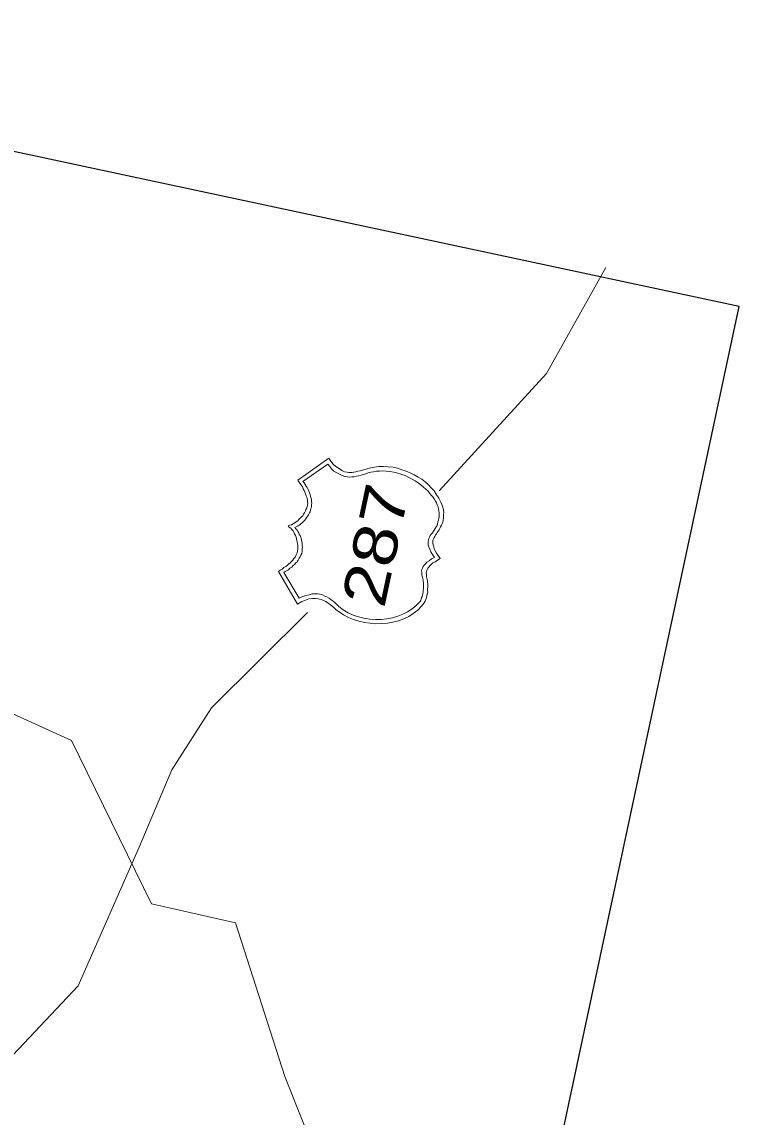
# Model space of a CAD drawing. Extents: x 2363411 to 2369126, y 6976878 to 6988319.
# Drawn here: x 2368470 to 2368553.7, y 6988102.7 to 6988230.5 of the extents above; entities that cross this region are included whole.
import ezdxf

# ---------------------------------------------------------------- set-up
doc = ezdxf.new("R2010")
doc.units = 0
doc.header["$LTSCALE"] = 2
doc.layers.add('62', color=7, linetype='Continuous', lineweight=13)
doc.layers.add('63', color=7, linetype='Continuous', lineweight=13)

msp = doc.modelspace()

# ---------------------------------------------------------------- linework, layer by layer
at = {"layer": '62'}
for p, q in [((2368538.15, 6988201.858), (2368531.227, 6988189.506)), ((2368531.227, 6988189.506), (2368518.7, 6988175.776)), ((2368492.126, 6988150.482), (2368503.332, 6988161.574))]:
    msp.add_line(p, q, dxfattribs=at)
at = {"layer": '62', "lineweight": 25}
msp.add_lwpolyline([(2368004.774, 6987854.862), (2368459.776, 6987757.642), (2368553.719, 6988197.31), (2368098.715, 6988294.53)], dxfattribs=at)
at = {"layer": '62'}
for points in [[(2368423.495, 6988182.612), (2368431.049, 6988175.317), (2368445.358, 6988162.592), (2368462.419, 6988152.736), (2368475.776, 6988146.66), (2368485.116, 6988127.592), (2368494.927, 6988125.354), (2368500.711, 6988107.416), (2368506.585, 6988092.7), (2368510.293, 6988075.479), (2368509.748, 6988052.675), (2368510.031, 6988033.104), (2368510.965, 6988011.643), (2368511.296, 6987998.756)], [(2368502.19, 6988162.579), (2368499.944, 6988166.392), (2368500.158, 6988166.532), (2368500.394, 6988166.664), (2368500.589, 6988166.829), (2368500.799, 6988166.946), (2368500.995, 6988167.114), (2368501.166, 6988167.26), (2368501.334, 6988167.408), (2368501.509, 6988167.577), (2368501.631, 6988167.713), (2368501.76, 6988167.892), (2368501.887, 6988168.049), (2368501.974, 6988168.239), (2368502.055, 6988168.405), (2368502.129, 6988168.549), (2368502.179, 6988168.77), (2368502.221, 6988168.967), (2368502.205, 6988169.11), (2368502.192, 6988169.272), (2368502.208, 6988169.452), (2368502.18, 6988169.643), (2368502.152, 6988169.835), (2368502.097, 6988170.006), (2368502.069, 6988170.198), (2368502.019, 6988170.391), (2368501.92, 6988170.573), (2368501.826, 6988170.778), (2368501.727, 6988170.96), (2368501.65, 6988171.136), (2368501.517, 6988171.281), (2368501.393, 6988171.445), (2368501.209, 6988171.554), (2368501.078, 6988171.696), (2368501.254, 6988171.773), (2368501.477, 6988171.842), (2368501.681, 6988171.936), (2368501.843, 6988172.04), (2368502.03, 6988172.162), (2368502.199, 6988172.307), (2368502.34, 6988172.439), (2368502.489, 6988172.591), (2368502.635, 6988172.742), (2368502.778, 6988172.875), (2368502.871, 6988173.084), (2368502.991, 6988173.222), (2368503.088, 6988173.453), (2368503.164, 6988173.598), (2368503.256, 6988173.808), (2368503.315, 6988173.981), (2368503.347, 6988174.134), (2368503.366, 6988174.336), (2368503.33, 6988174.483), (2368503.329, 6988174.688), (2368503.299, 6988174.88), (2368503.244, 6988175.054), (2368503.191, 6988175.227), (2368503.121, 6988175.448), (2368503.022, 6988175.631), (2368502.951, 6988175.828), (2368502.828, 6988176.016), (2368502.739, 6988176.242), (2368502.62, 6988176.431), (2368502.479, 6988176.643), (2368502.336, 6988176.835), (2368502.22, 6988177.044), (2368505.829, 6988179.61), (2368506.076, 6988179.257), (2368506.322, 6988178.905), (2368506.653, 6988178.626), (2368507.017, 6988178.389), (2368507.359, 6988178.154), (2368507.674, 6988178.015), (2368507.96, 6988177.956), (2368508.158, 6988177.914), (2368508.345, 6988177.921), (2368508.555, 6988177.946), (2368508.747, 6988177.972), (2368508.985, 6988178.013), (2368509.227, 6988178.076), (2368509.472, 6988178.14), (2368509.742, 6988178.222), (2368510.012, 6988178.301), (2368510.306, 6988178.375), (2368510.575, 6988178.457), (2368510.886, 6988178.505), (2368511.151, 6988178.563), (2368511.412, 6988178.599), (2368511.671, 6988178.636), (2368511.95, 6988178.646), (2368512.2, 6988178.637), (2368512.766, 6988178.586), (2368513.331, 6988178.537), (2368513.836, 6988178.427), (2368514.349, 6988178.248), (2368514.868, 6988178.092), (2368515.335, 6988177.9), (2368515.79, 6988177.664), (2368516.24, 6988177.406), (2368516.669, 6988177.155), (2368517.085, 6988176.835)], [(2368517.583, 6988175.51), (2368517.407, 6988175.754), (2368517.136, 6988175.998), (2368516.866, 6988176.238), (2368516.573, 6988176.484), (2368516.255, 6988176.714), (2368515.913, 6988176.948), (2368515.568, 6988177.161), (2368515.171, 6988177.358), (2368514.756, 6988177.564), (2368514.347, 6988177.696), (2368513.899, 6988177.859), (2368513.436, 6988177.962), (2368512.949, 6988178.042), (2368512.52, 6988178.086), (2368512.116, 6988178.128), (2368511.763, 6988178.089), (2368511.392, 6988178.074), (2368511.054, 6988178.009), (2368510.745, 6988177.961), (2368510.431, 6988177.889), (2368510.135, 6988177.79), (2368509.837, 6988177.694), (2368509.588, 6988177.609), (2368509.323, 6988177.551), (2368509.058, 6988177.493), (2368508.771, 6988177.438), (2368508.537, 6988177.42), (2368508.279, 6988177.406), (2368508.006, 6988177.417), (2368507.693, 6988177.461), (2368507.377, 6988177.598), (2368507.061, 6988177.735), (2368506.75, 6988177.894), (2368506.427, 6988178.1), (2368506.177, 6988178.337), (2368505.938, 6988178.619), (2368505.699, 6988178.9), (2368502.809, 6988176.895), (2368502.931, 6988176.71), (2368503.057, 6988176.542), (2368503.2, 6988176.352), (2368503.3, 6988176.169), (2368503.415, 6988175.962), (2368503.487, 6988175.761), (2368503.56, 6988175.563), (2368503.632, 6988175.361), (2368503.7, 6988175.14), (2368503.772, 6988174.941), (2368503.796, 6988174.727), (2368503.802, 6988174.544), (2368503.832, 6988174.351), (2368503.82, 6988174.194), (2368503.81, 6988174.037), (2368503.8, 6988173.876), (2368503.744, 6988173.728), (2368503.683, 6988173.555), (2368503.642, 6988173.359), (2368503.564, 6988173.212), (2368503.451, 6988173.007), (2368503.375, 6988172.862), (2368503.27, 6988172.7), (2368503.142, 6988172.521), (2368503.019, 6988172.386), (2368502.889, 6988172.207), (2368502.752, 6988172.099), (2368502.585, 6988171.973), (2368502.438, 6988171.821), (2368502.256, 6988171.723), (2368502.075, 6988171.622), (2368501.87, 6988171.529), (2368501.995, 6988171.363), (2368502.143, 6988171.195), (2368502.225, 6988171.038), (2368502.329, 6988170.877), (2368502.384, 6988170.705), (2368502.47, 6988170.571), (2368502.544, 6988170.371), (2368502.603, 6988170.221), (2368502.637, 6988170.052), (2368502.688, 6988169.857), (2368502.703, 6988169.715), (2368502.708, 6988169.532), (2368502.72, 6988169.368), (2368502.753, 6988169.199), (2368502.715, 6988169.023), (2368502.726, 6988168.861), (2368502.716, 6988168.7), (2368502.668, 6988168.481), (2368502.56, 6988168.298), (2368502.49, 6988168.081), (2368502.364, 6988167.924), (2368502.253, 6988167.717), (2368502.117, 6988167.519), (2368501.973, 6988167.386), (2368501.817, 6988167.19), (2368501.643, 6988167.021), (2368501.495, 6988166.869), (2368501.284, 6988166.75), (2368501.112, 6988166.582), (2368500.903, 6988166.463)], [(2368517.085, 6988176.835), (2368517.45, 6988176.503), (2368517.764, 6988176.138), (2368518.127, 6988175.784), (2368518.397, 6988175.334), (2368518.68, 6988174.929), (2368518.904, 6988174.469), (2368519.01, 6988174.215), (2368519.1, 6988173.991), (2368519.162, 6988173.745), (2368519.203, 6988173.507), (2368519.25, 6988173.29), (2368519.224, 6988173.065), (2368519.218, 6988172.812), (2368519.218, 6988172.608), (2368519.166, 6988172.363), (2368519.119, 6988172.142), (2368519.054, 6988171.952), (2368518.995, 6988171.78), (2368518.882, 6988171.575), (2368518.801, 6988171.407), (2368518.72, 6988171.24), (2368518.593, 6988171.083), (2368518.49, 6988170.923), (2368518.387, 6988170.759), (2368518.292, 6988170.642), (2368518.19, 6988170.48), (2368518.138, 6988170.352), (2368518.056, 6988170.185), (2368517.975, 6988170.021), (2368517.965, 6988169.859), (2368517.972, 6988169.674), (2368517.994, 6988169.462), (2368518.067, 6988169.263), (2368518.134, 6988169.042), (2368518.241, 6988168.788), (2368518.392, 6988168.526), (2368518.604, 6988168.227), (2368518.833, 6988167.902), (2368518.513, 6988167.693), (2368518.247, 6988167.523), (2368517.984, 6988167.37), (2368517.783, 6988167.184), (2368517.62, 6988167.057), (2368517.494, 6988166.9), (2368517.393, 6988166.76), (2368517.318, 6988166.617), (2368517.266, 6988166.489), (2368517.234, 6988166.334), (2368517.206, 6988166.203), (2368517.217, 6988166.041), (2368517.237, 6988165.922), (2368517.227, 6988165.761), (2368517.282, 6988165.59), (2368517.297, 6988165.447), (2368517.335, 6988165.302), (2368517.347, 6988165.138), (2368517.374, 6988164.948), (2368517.376, 6988164.739), (2368517.382, 6988164.554), (2368517.362, 6988164.351), (2368517.366, 6988164.144), (2368517.372, 6988163.961), (2368517.323, 6988163.74), (2368517.281, 6988163.541), (2368517.239, 6988163.341), (2368517.145, 6988163.109), (2368517.057, 6988162.92), (2368516.944, 6988162.715), (2368516.809, 6988162.514), (2368516.651, 6988162.317), (2368516.213, 6988161.881), (2368515.691, 6988161.485), (2368515.153, 6988161.118), (2368514.566, 6988160.852), (2368513.943, 6988160.617), (2368513.308, 6988160.454), (2368512.668, 6988160.362), (2368511.987, 6988160.299), (2368511.317, 6988160.281), (2368510.659, 6988160.329), (2368509.989, 6988160.427), (2368509.35, 6988160.562), (2368508.725, 6988160.765), (2368508.137, 6988161.007), (2368507.556, 6988161.315), (2368507.053, 6988161.652), (2368506.851, 6988161.787), (2368506.633, 6988161.948), (2368506.441, 6988162.128), (2368506.207, 6988162.315), (2368505.972, 6988162.507), (2368505.736, 6988162.692), (2368505.494, 6988162.861), (2368505.223, 6988162.986), (2368504.929, 6988163.118), (2368504.598, 6988163.191), (2368504.264, 6988163.238), (2368503.914, 6988163.221), (2368503.512, 6988163.169), (2368503.096, 6988163.05)], [(2368500.583, 6988166.258), (2368502.357, 6988163.255), (2368502.767, 6988163.443), (2368503.166, 6988163.587), (2368503.528, 6988163.671), (2368503.868, 6988163.76), (2368504.212, 6988163.754), (2368504.512, 6988163.76), (2368504.78, 6988163.725), (2368505.085, 6988163.639), (2368505.358, 6988163.511), (2368505.611, 6988163.41), (2368505.858, 6988163.265), (2368506.094, 6988163.076), (2368506.333, 6988162.912), (2368506.568, 6988162.723), (2368506.779, 6988162.518), (2368507.009, 6988162.306), (2368507.519, 6988161.898), (2368508.095, 6988161.568), (2368508.655, 6988161.287), (2368509.3, 6988161.08), (2368509.934, 6988160.922), (2368510.598, 6988160.802), (2368511.283, 6988160.771), (2368511.927, 6988160.772), (2368512.585, 6988160.838), (2368513.258, 6988160.97), (2368513.876, 6988161.162), (2368514.474, 6988161.379), (2368515.018, 6988161.676), (2368515.548, 6988162.001), (2368516, 6988162.387), (2368516.406, 6988162.783), (2368516.473, 6988162.883), (2368516.569, 6988163.001), (2368516.622, 6988163.152), (2368516.66, 6988163.328), (2368516.71, 6988163.454), (2368516.749, 6988163.632), (2368516.787, 6988163.808), (2368516.824, 6988163.984), (2368516.845, 6988164.186), (2368516.876, 6988164.341), (2368516.876, 6988164.545), (2368516.89, 6988164.728), (2368516.881, 6988164.892), (2368516.874, 6988165.077), (2368516.84, 6988165.246), (2368516.846, 6988165.382), (2368516.787, 6988165.534), (2368516.752, 6988165.701), (2368516.713, 6988165.826), (2368516.677, 6988165.993), (2368516.667, 6988166.157), (2368516.674, 6988166.294), (2368516.663, 6988166.456), (2368516.694, 6988166.611), (2368516.771, 6988166.756), (2368516.858, 6988166.946), (2368516.939, 6988167.111), (2368517.108, 6988167.257), (2368517.288, 6988167.451), (2368517.555, 6988167.623), (2368517.831, 6988167.84), (2368518.148, 6988168.026), (2368517.922, 6988168.373), (2368517.737, 6988168.689), (2368517.613, 6988168.967), (2368517.511, 6988169.244), (2368517.442, 6988169.466), (2368517.441, 6988169.673), (2368517.434, 6988169.858), (2368517.481, 6988170.079), (2368517.514, 6988170.233), (2368517.591, 6988170.377), (2368517.677, 6988170.565), (2368517.78, 6988170.727), (2368517.902, 6988170.864), (2368518.004, 6988171.025), (2368518.115, 6988171.207), (2368518.246, 6988171.388), (2368518.354, 6988171.572), (2368518.46, 6988171.753), (2368518.526, 6988171.948), (2368518.572, 6988172.169), (2368518.637, 6988172.364), (2368518.663, 6988172.588), (2368518.704, 6988172.785), (2368518.707, 6988173.014), (2368518.711, 6988173.244), (2368518.687, 6988173.456), (2368518.624, 6988173.7), (2368518.578, 6988173.917), (2368518.488, 6988174.142), (2368518.404, 6988174.391), (2368518.265, 6988174.605), (2368518.108, 6988174.845), (2368517.993, 6988175.054), (2368517.788, 6988175.282), (2368517.583, 6988175.51)], [(2368500.903, 6988166.463), (2368500.744, 6988166.36), (2368500.583, 6988166.258)], [(2368503.096, 6988163.05), (2368502.666, 6988162.865), (2368502.19, 6988162.579)], [(2368492.126, 6988150.482), (2368487.488, 6988143.215), (2368483.673, 6988134.181), (2368476.579, 6988118.002), (2368468.319, 6988109.277), (2368462.564, 6988103.439), (2368454.914, 6988095.96), (2368443.897, 6988089.32), (2368432.645, 6988085.443), (2368420.226, 6988082.021), (2368405.209, 6988076.579), (2368395.275, 6988071.108), (2368385.769, 6988067.316), (2368374.006, 6988063.41), (2368368.396, 6988060.537), (2368354.465, 6988056.288)]]:
    msp.add_lwpolyline(points, dxfattribs=at)
at = {"layer": '63'}
for p, q in [((2368538.15, 6988201.858), (2368531.227, 6988189.506)), ((2368531.227, 6988189.506), (2368518.7, 6988175.776)), ((2368492.126, 6988150.482), (2368503.332, 6988161.574))]:
    msp.add_line(p, q, dxfattribs=at)
at = {"layer": '63', "lineweight": 25}
msp.add_lwpolyline([(2368004.774, 6987854.862), (2368459.776, 6987757.642), (2368553.719, 6988197.31), (2368098.715, 6988294.53)], dxfattribs=at)
at = {"layer": '63'}
for points in [[(2368423.495, 6988182.612), (2368431.049, 6988175.317), (2368445.358, 6988162.592), (2368462.419, 6988152.736), (2368475.776, 6988146.66), (2368485.116, 6988127.592), (2368494.927, 6988125.354), (2368500.711, 6988107.416), (2368506.585, 6988092.7), (2368510.293, 6988075.479), (2368509.748, 6988052.675), (2368510.031, 6988033.104), (2368510.965, 6988011.643), (2368511.296, 6987998.756)], [(2368502.19, 6988162.579), (2368499.944, 6988166.392), (2368500.158, 6988166.532), (2368500.394, 6988166.664), (2368500.589, 6988166.829), (2368500.799, 6988166.946), (2368500.995, 6988167.114), (2368501.166, 6988167.26), (2368501.334, 6988167.408), (2368501.509, 6988167.577), (2368501.631, 6988167.713), (2368501.76, 6988167.892), (2368501.887, 6988168.049), (2368501.974, 6988168.239), (2368502.055, 6988168.405), (2368502.129, 6988168.549), (2368502.179, 6988168.77), (2368502.221, 6988168.967), (2368502.205, 6988169.11), (2368502.192, 6988169.272), (2368502.208, 6988169.452), (2368502.18, 6988169.643), (2368502.152, 6988169.835), (2368502.097, 6988170.006), (2368502.069, 6988170.198), (2368502.019, 6988170.391), (2368501.92, 6988170.573), (2368501.826, 6988170.778), (2368501.727, 6988170.96), (2368501.65, 6988171.136), (2368501.517, 6988171.281), (2368501.393, 6988171.445), (2368501.209, 6988171.554), (2368501.078, 6988171.696), (2368501.254, 6988171.773), (2368501.477, 6988171.842), (2368501.681, 6988171.936), (2368501.843, 6988172.04), (2368502.03, 6988172.162), (2368502.199, 6988172.307), (2368502.34, 6988172.439), (2368502.489, 6988172.591), (2368502.635, 6988172.742), (2368502.778, 6988172.875), (2368502.871, 6988173.084), (2368502.991, 6988173.222), (2368503.088, 6988173.453), (2368503.164, 6988173.598), (2368503.256, 6988173.808), (2368503.315, 6988173.981), (2368503.347, 6988174.134), (2368503.366, 6988174.336), (2368503.33, 6988174.483), (2368503.329, 6988174.688), (2368503.299, 6988174.88), (2368503.244, 6988175.054), (2368503.191, 6988175.227), (2368503.121, 6988175.448), (2368503.022, 6988175.631), (2368502.951, 6988175.828), (2368502.828, 6988176.016), (2368502.739, 6988176.242), (2368502.62, 6988176.431), (2368502.479, 6988176.643), (2368502.336, 6988176.835), (2368502.22, 6988177.044), (2368505.829, 6988179.61), (2368506.076, 6988179.257), (2368506.322, 6988178.905), (2368506.653, 6988178.626), (2368507.017, 6988178.389), (2368507.359, 6988178.154), (2368507.674, 6988178.015), (2368507.96, 6988177.956), (2368508.158, 6988177.914), (2368508.345, 6988177.921), (2368508.555, 6988177.946), (2368508.747, 6988177.972), (2368508.985, 6988178.013), (2368509.227, 6988178.076), (2368509.472, 6988178.14), (2368509.742, 6988178.222), (2368510.012, 6988178.301), (2368510.306, 6988178.375), (2368510.575, 6988178.457), (2368510.886, 6988178.505), (2368511.151, 6988178.563), (2368511.412, 6988178.599), (2368511.671, 6988178.636), (2368511.95, 6988178.646), (2368512.2, 6988178.637), (2368512.766, 6988178.586), (2368513.331, 6988178.537), (2368513.836, 6988178.427), (2368514.349, 6988178.248), (2368514.868, 6988178.092), (2368515.335, 6988177.9), (2368515.79, 6988177.664), (2368516.24, 6988177.406), (2368516.669, 6988177.155), (2368517.085, 6988176.835)], [(2368517.583, 6988175.51), (2368517.407, 6988175.754), (2368517.136, 6988175.998), (2368516.866, 6988176.238), (2368516.573, 6988176.484), (2368516.255, 6988176.714), (2368515.913, 6988176.948), (2368515.568, 6988177.161), (2368515.171, 6988177.358), (2368514.756, 6988177.564), (2368514.347, 6988177.696), (2368513.899, 6988177.859), (2368513.436, 6988177.962), (2368512.949, 6988178.042), (2368512.52, 6988178.086), (2368512.116, 6988178.128), (2368511.763, 6988178.089), (2368511.392, 6988178.074), (2368511.054, 6988178.009), (2368510.745, 6988177.961), (2368510.431, 6988177.889), (2368510.135, 6988177.79), (2368509.837, 6988177.694), (2368509.588, 6988177.609), (2368509.323, 6988177.551), (2368509.058, 6988177.493), (2368508.771, 6988177.438), (2368508.537, 6988177.42), (2368508.279, 6988177.406), (2368508.006, 6988177.417), (2368507.693, 6988177.461), (2368507.377, 6988177.598), (2368507.061, 6988177.735), (2368506.75, 6988177.894), (2368506.427, 6988178.1), (2368506.177, 6988178.337), (2368505.938, 6988178.619), (2368505.699, 6988178.9), (2368502.809, 6988176.895), (2368502.931, 6988176.71), (2368503.057, 6988176.542), (2368503.2, 6988176.352), (2368503.3, 6988176.169), (2368503.415, 6988175.962), (2368503.487, 6988175.761), (2368503.56, 6988175.563), (2368503.632, 6988175.361), (2368503.7, 6988175.14), (2368503.772, 6988174.941), (2368503.796, 6988174.727), (2368503.802, 6988174.544), (2368503.832, 6988174.351), (2368503.82, 6988174.194), (2368503.81, 6988174.037), (2368503.8, 6988173.876), (2368503.744, 6988173.728), (2368503.683, 6988173.555), (2368503.642, 6988173.359), (2368503.564, 6988173.212), (2368503.451, 6988173.007), (2368503.375, 6988172.862), (2368503.27, 6988172.7), (2368503.142, 6988172.521), (2368503.019, 6988172.386), (2368502.889, 6988172.207), (2368502.752, 6988172.099), (2368502.585, 6988171.973), (2368502.438, 6988171.821), (2368502.256, 6988171.723), (2368502.075, 6988171.622), (2368501.87, 6988171.529), (2368501.995, 6988171.363), (2368502.143, 6988171.195), (2368502.225, 6988171.038), (2368502.329, 6988170.877), (2368502.384, 6988170.705), (2368502.47, 6988170.571), (2368502.544, 6988170.371), (2368502.603, 6988170.221), (2368502.637, 6988170.052), (2368502.688, 6988169.857), (2368502.703, 6988169.715), (2368502.708, 6988169.532), (2368502.72, 6988169.368), (2368502.753, 6988169.199), (2368502.715, 6988169.023), (2368502.726, 6988168.861), (2368502.716, 6988168.7), (2368502.668, 6988168.481), (2368502.56, 6988168.298), (2368502.49, 6988168.081), (2368502.364, 6988167.924), (2368502.253, 6988167.717), (2368502.117, 6988167.519), (2368501.973, 6988167.386), (2368501.817, 6988167.19), (2368501.643, 6988167.021), (2368501.495, 6988166.869), (2368501.284, 6988166.75), (2368501.112, 6988166.582), (2368500.903, 6988166.463)], [(2368517.085, 6988176.835), (2368517.45, 6988176.503), (2368517.764, 6988176.138), (2368518.127, 6988175.784), (2368518.397, 6988175.334), (2368518.68, 6988174.929), (2368518.904, 6988174.469), (2368519.01, 6988174.215), (2368519.1, 6988173.991), (2368519.162, 6988173.745), (2368519.203, 6988173.507), (2368519.25, 6988173.29), (2368519.224, 6988173.065), (2368519.218, 6988172.812), (2368519.218, 6988172.608), (2368519.166, 6988172.363), (2368519.119, 6988172.142), (2368519.054, 6988171.952), (2368518.995, 6988171.78), (2368518.882, 6988171.575), (2368518.801, 6988171.407), (2368518.72, 6988171.24), (2368518.593, 6988171.083), (2368518.49, 6988170.923), (2368518.387, 6988170.759), (2368518.292, 6988170.642), (2368518.19, 6988170.48), (2368518.138, 6988170.352), (2368518.056, 6988170.185), (2368517.975, 6988170.021), (2368517.965, 6988169.859), (2368517.972, 6988169.674), (2368517.994, 6988169.462), (2368518.067, 6988169.263), (2368518.134, 6988169.042), (2368518.241, 6988168.788), (2368518.392, 6988168.526), (2368518.604, 6988168.227), (2368518.833, 6988167.902), (2368518.513, 6988167.693), (2368518.247, 6988167.523), (2368517.984, 6988167.37), (2368517.783, 6988167.184), (2368517.62, 6988167.057), (2368517.494, 6988166.9), (2368517.393, 6988166.76), (2368517.318, 6988166.617), (2368517.266, 6988166.489), (2368517.234, 6988166.334), (2368517.206, 6988166.203), (2368517.217, 6988166.041), (2368517.237, 6988165.922), (2368517.227, 6988165.761), (2368517.282, 6988165.59), (2368517.297, 6988165.447), (2368517.335, 6988165.302), (2368517.347, 6988165.138), (2368517.374, 6988164.948), (2368517.376, 6988164.739), (2368517.382, 6988164.554), (2368517.362, 6988164.351), (2368517.366, 6988164.144), (2368517.372, 6988163.961), (2368517.323, 6988163.74), (2368517.281, 6988163.541), (2368517.239, 6988163.341), (2368517.145, 6988163.109), (2368517.057, 6988162.92), (2368516.944, 6988162.715), (2368516.809, 6988162.514), (2368516.651, 6988162.317), (2368516.213, 6988161.881), (2368515.691, 6988161.485), (2368515.153, 6988161.118), (2368514.566, 6988160.852), (2368513.943, 6988160.617), (2368513.308, 6988160.454), (2368512.668, 6988160.362), (2368511.987, 6988160.299), (2368511.317, 6988160.281), (2368510.659, 6988160.329), (2368509.989, 6988160.427), (2368509.35, 6988160.562), (2368508.725, 6988160.765), (2368508.137, 6988161.007), (2368507.556, 6988161.315), (2368507.053, 6988161.652), (2368506.851, 6988161.787), (2368506.633, 6988161.948), (2368506.441, 6988162.128), (2368506.207, 6988162.315), (2368505.972, 6988162.507), (2368505.736, 6988162.692), (2368505.494, 6988162.861), (2368505.223, 6988162.986), (2368504.929, 6988163.118), (2368504.598, 6988163.191), (2368504.264, 6988163.238), (2368503.914, 6988163.221), (2368503.512, 6988163.169), (2368503.096, 6988163.05)], [(2368500.583, 6988166.258), (2368502.357, 6988163.255), (2368502.767, 6988163.443), (2368503.166, 6988163.587), (2368503.528, 6988163.671), (2368503.868, 6988163.76), (2368504.212, 6988163.754), (2368504.512, 6988163.76), (2368504.78, 6988163.725), (2368505.085, 6988163.639), (2368505.358, 6988163.511), (2368505.611, 6988163.41), (2368505.858, 6988163.265), (2368506.094, 6988163.076), (2368506.333, 6988162.912), (2368506.568, 6988162.723), (2368506.779, 6988162.518), (2368507.009, 6988162.306), (2368507.519, 6988161.898), (2368508.095, 6988161.568), (2368508.655, 6988161.287), (2368509.3, 6988161.08), (2368509.934, 6988160.922), (2368510.598, 6988160.802), (2368511.283, 6988160.771), (2368511.927, 6988160.772), (2368512.585, 6988160.838), (2368513.258, 6988160.97), (2368513.876, 6988161.162), (2368514.474, 6988161.379), (2368515.018, 6988161.676), (2368515.548, 6988162.001), (2368516, 6988162.387), (2368516.406, 6988162.783), (2368516.473, 6988162.883), (2368516.569, 6988163.001), (2368516.622, 6988163.152), (2368516.66, 6988163.328), (2368516.71, 6988163.454), (2368516.749, 6988163.632), (2368516.787, 6988163.808), (2368516.824, 6988163.984), (2368516.845, 6988164.186), (2368516.876, 6988164.341), (2368516.876, 6988164.545), (2368516.89, 6988164.728), (2368516.881, 6988164.892), (2368516.874, 6988165.077), (2368516.84, 6988165.246), (2368516.846, 6988165.382), (2368516.787, 6988165.534), (2368516.752, 6988165.701), (2368516.713, 6988165.826), (2368516.677, 6988165.993), (2368516.667, 6988166.157), (2368516.674, 6988166.294), (2368516.663, 6988166.456), (2368516.694, 6988166.611), (2368516.771, 6988166.756), (2368516.858, 6988166.946), (2368516.939, 6988167.111), (2368517.108, 6988167.257), (2368517.288, 6988167.451), (2368517.555, 6988167.623), (2368517.831, 6988167.84), (2368518.148, 6988168.026), (2368517.922, 6988168.373), (2368517.737, 6988168.689), (2368517.613, 6988168.967), (2368517.511, 6988169.244), (2368517.442, 6988169.466), (2368517.441, 6988169.673), (2368517.434, 6988169.858), (2368517.481, 6988170.079), (2368517.514, 6988170.233), (2368517.591, 6988170.377), (2368517.677, 6988170.565), (2368517.78, 6988170.727), (2368517.902, 6988170.864), (2368518.004, 6988171.025), (2368518.115, 6988171.207), (2368518.246, 6988171.388), (2368518.354, 6988171.572), (2368518.46, 6988171.753), (2368518.526, 6988171.948), (2368518.572, 6988172.169), (2368518.637, 6988172.364), (2368518.663, 6988172.588), (2368518.704, 6988172.785), (2368518.707, 6988173.014), (2368518.711, 6988173.244), (2368518.687, 6988173.456), (2368518.624, 6988173.7), (2368518.578, 6988173.917), (2368518.488, 6988174.142), (2368518.404, 6988174.391), (2368518.265, 6988174.605), (2368518.108, 6988174.845), (2368517.993, 6988175.054), (2368517.788, 6988175.282), (2368517.583, 6988175.51)], [(2368500.903, 6988166.463), (2368500.744, 6988166.36), (2368500.583, 6988166.258)], [(2368503.096, 6988163.05), (2368502.666, 6988162.865), (2368502.19, 6988162.579)], [(2368492.126, 6988150.482), (2368487.488, 6988143.215), (2368483.673, 6988134.181), (2368476.579, 6988118.002), (2368468.319, 6988109.277), (2368462.564, 6988103.439), (2368454.914, 6988095.96), (2368443.897, 6988089.32), (2368432.645, 6988085.443), (2368420.226, 6988082.021), (2368405.209, 6988076.579), (2368395.275, 6988071.108), (2368385.769, 6988067.316), (2368374.006, 6988063.41), (2368368.396, 6988060.537), (2368354.465, 6988056.288)]]:
    msp.add_lwpolyline(points, dxfattribs=at)

# ---------------------------------------------------------------- texts
at = {"layer": '62', "width": 1.25}
msp.add_text('287', height=5.099, rotation=77.939, dxfattribs=at).set_placement((2368512.274, 6988161.965))
at = {"layer": '63', "width": 1.25}
msp.add_text('287', height=5.099, rotation=77.939, dxfattribs=at).set_placement((2368512.274, 6988161.965))

doc.saveas('drawing.dxf')
